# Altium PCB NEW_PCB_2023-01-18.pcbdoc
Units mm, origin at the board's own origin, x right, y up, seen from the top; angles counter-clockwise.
Board outline 51.82 x 75.44 mm, 2 copper layers (Top Layer, Bottom Layer); 4 components, 20 nets, 43 pads, 0 vias.
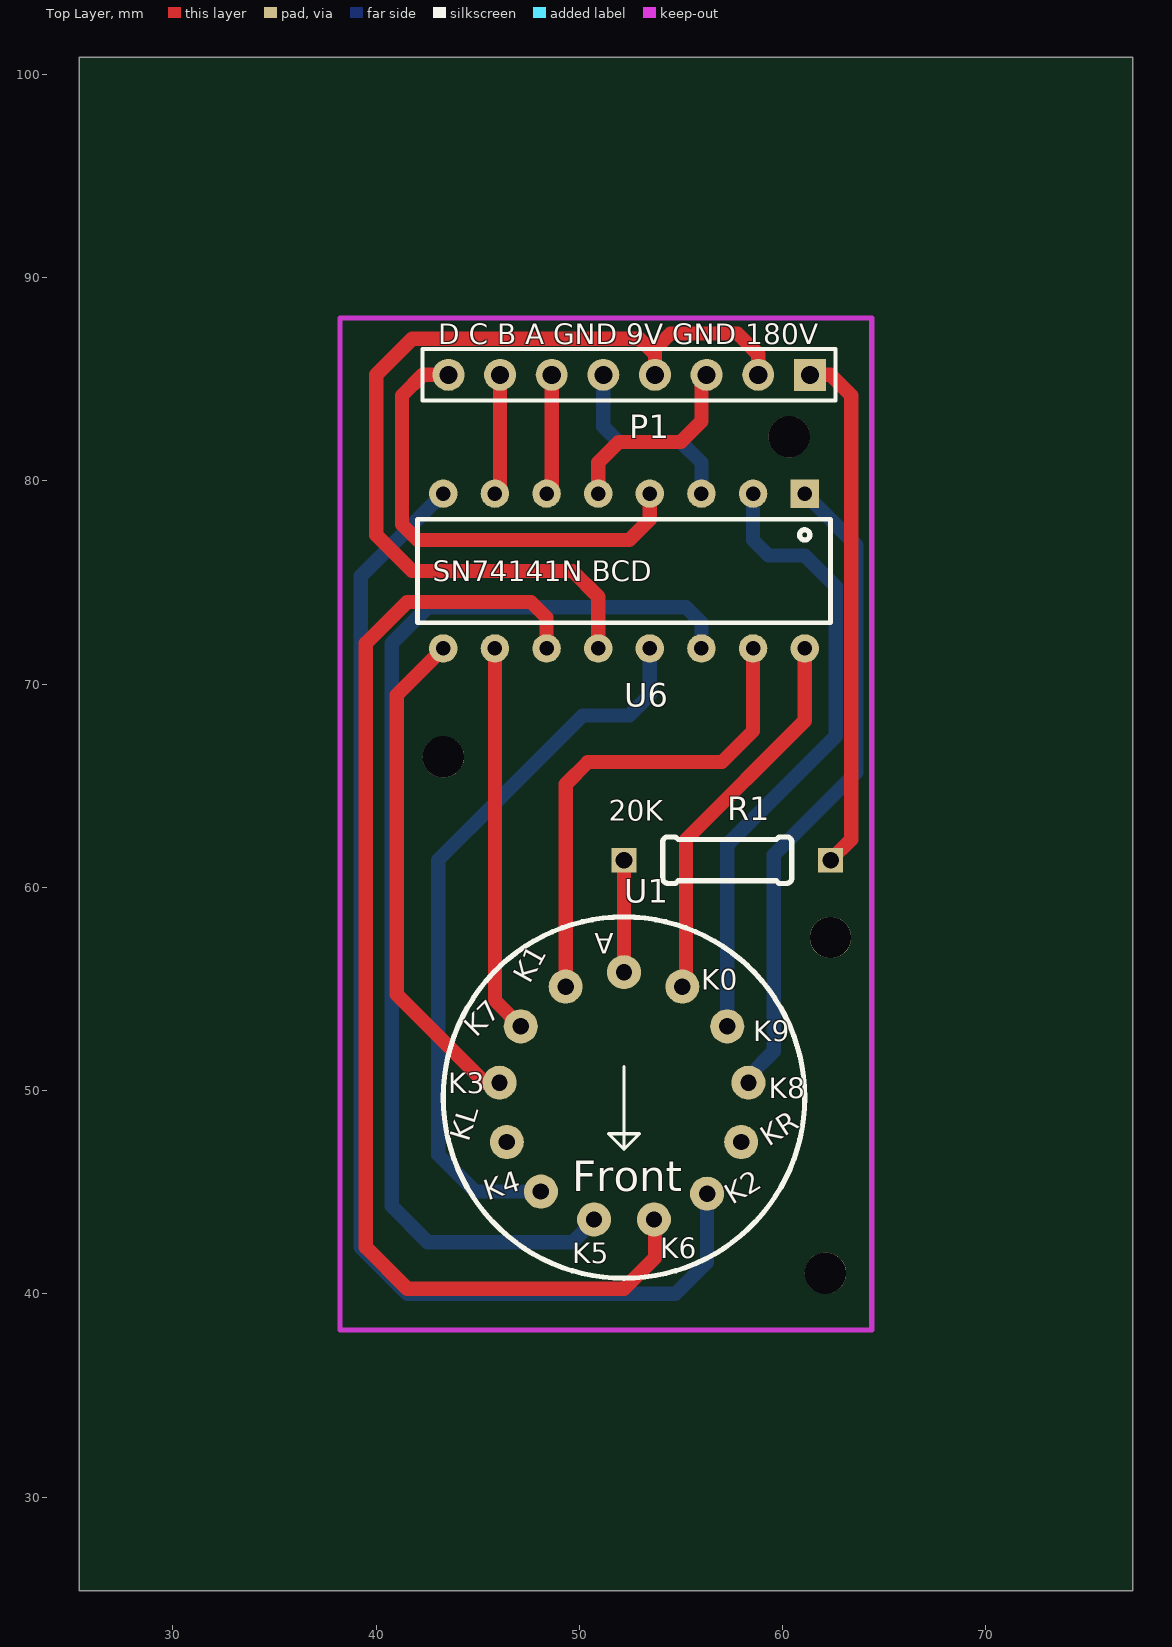
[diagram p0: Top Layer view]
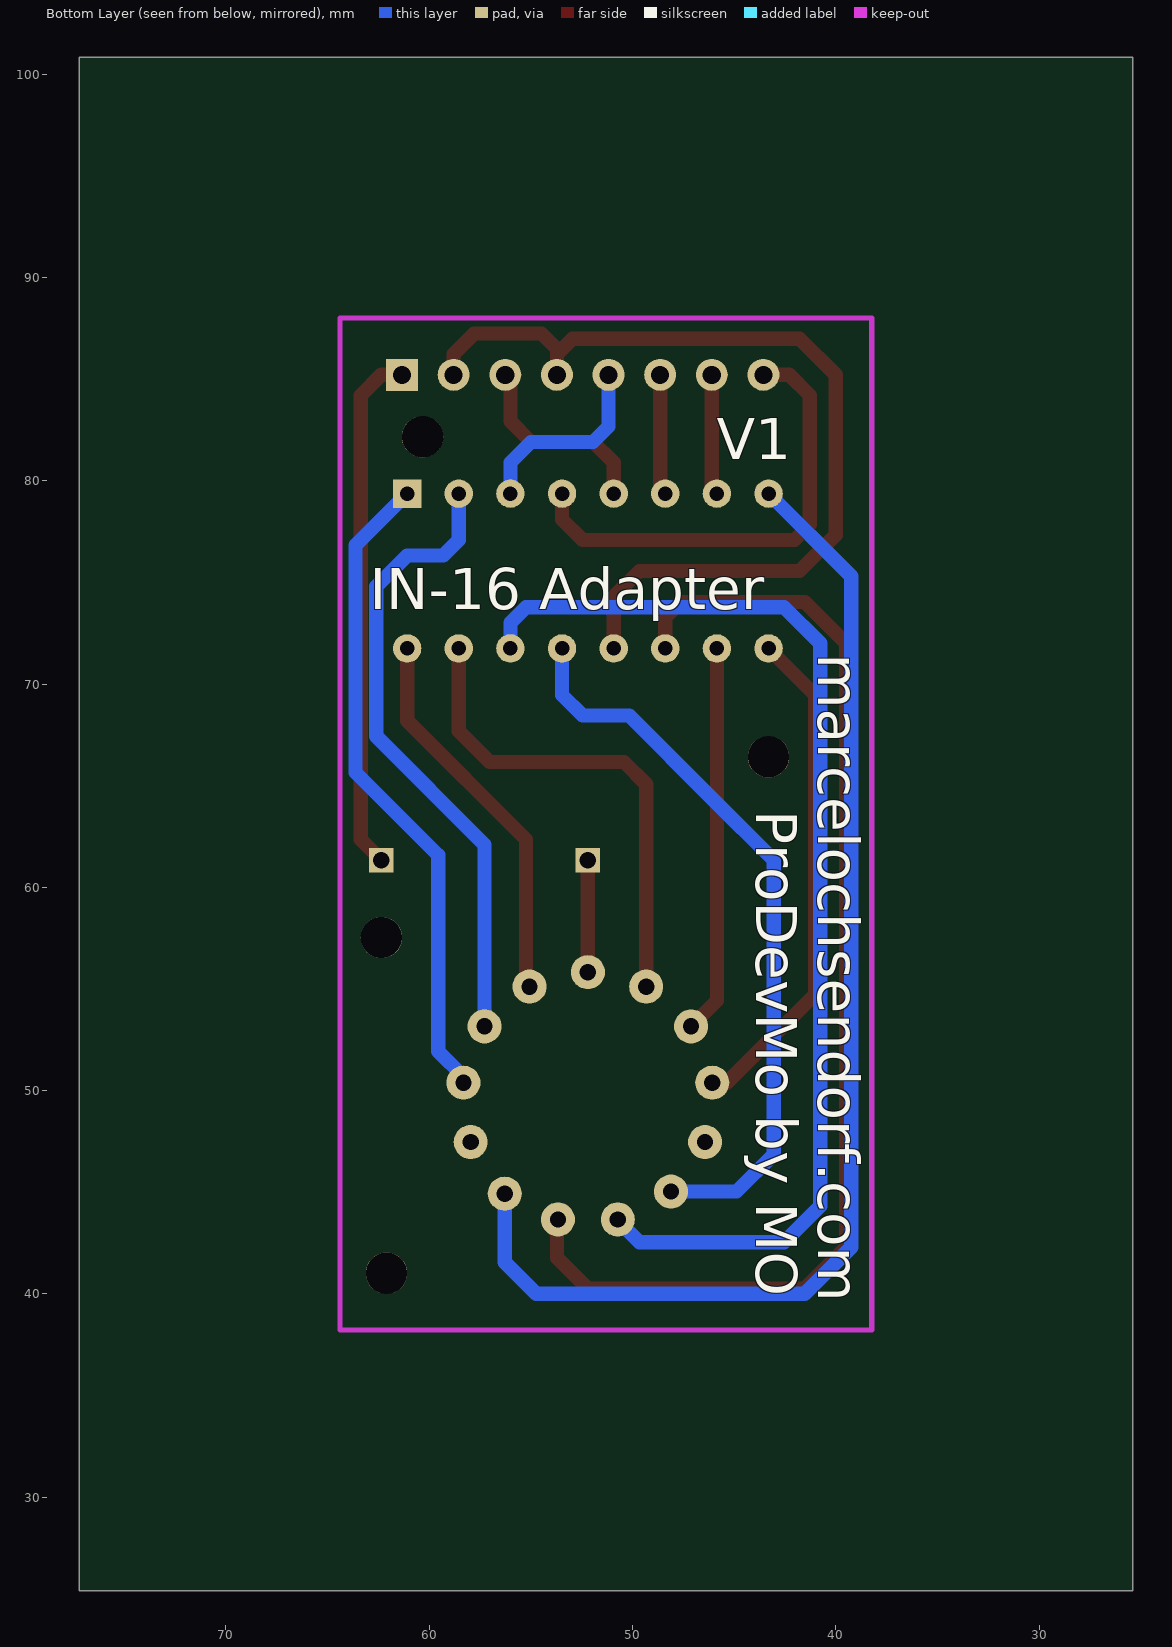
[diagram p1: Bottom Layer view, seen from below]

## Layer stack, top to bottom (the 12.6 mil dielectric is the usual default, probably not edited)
Top Layer: signal copper (thickness not stored)
Dielectric: dielectric 0.32, FR-4, Dk 4.8
Bottom Layer: signal copper (thickness not stored)

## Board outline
77.216,25.4 25.4,25.4 25.4,100.838 77.216,100.838

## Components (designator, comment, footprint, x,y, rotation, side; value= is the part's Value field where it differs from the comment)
P1 "Header2.54mm 1*8P" HDR-8X1/2.54 53.721,85.217 r180 top
R1 "RESISTOR" RTH025W 57.277,61.341 r0 top
U1 "IN-16" "IN-16 FOOTPRINT" 52.197,49.657 r0 top
U6 "SN74141 BCD to Decimal" DIP16 61.087,79.375 r180 top

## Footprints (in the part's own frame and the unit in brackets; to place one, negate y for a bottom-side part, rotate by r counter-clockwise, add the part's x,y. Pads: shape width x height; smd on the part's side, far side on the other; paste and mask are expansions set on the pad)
DIP16 [mil]
  rect 55x55 hole 28: 1(0,0)
  round 55 hole 28: 2(100,0) 3(200,0) 4(300,0) 5(400,0) 6(500,0) 7(600,0) 8(700,0) 9(700,300) 10(600,300) 11(500,300) 12(400,300) 13(300,300) 14(200,300) 15(100,300) 16(0,300)
  silkscreen extent -50,50 750,250
HDR-8X1/2.54 [mil]
  rect 62x62 hole 35: 1(-300,0)
  round 62 hole 35: 2(-200,0) 3(-100,0) 4(0,0) 5(100,0) 6(200,0) 7(300,0) 8(400,0)
  silkscreen extent -350,-50 450,50
"IN-16 FOOTPRINT" [mil]
  round 66 hole 31.5: 1(0,243) 2(-113,215) 3(-200,138) 4(-241,29) 5(-227,-86) 6(-161,-182) 7(-58,-236) 8(58,-236) 9(161,-186) 10(227,-86) 11(241,29) 12(200,138) 13(113,215)
  silkscreen extent -350,-350 350,350
RTH025W [mil]
  rect 47.7x47.7 hole 32: 1(-200,0) 2(200,0)
  silkscreen extent -125,-45 125,45

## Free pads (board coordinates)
  round 2.032 hole 2.032 unplated: ""(43.307,66.421) ""(60.325,82.169) ""(62.103,41.021) ""(62.357,57.531)

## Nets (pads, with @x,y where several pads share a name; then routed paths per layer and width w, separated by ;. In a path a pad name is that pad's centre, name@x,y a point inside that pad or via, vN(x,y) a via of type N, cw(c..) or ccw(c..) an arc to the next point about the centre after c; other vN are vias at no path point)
R1_2: P1.1 R1.2 | length 25.7
  Top Layer w0.7: P1.1 62.357,85.217 63.373,84.201 63.373,62.357 R1.2
U1_1: R1.1 U1.1 | length 5.5
  Top Layer w0.7: U1.1 R1.1
U1_2: U1.2 U6.15 | length 24.3
  Top Layer w0.7: U1.2 49.327,65.075 50.419,66.167 57.023,66.167 58.547,67.691 U6.15
U1_3: U1.3 U6.10 | length 19.1
  Top Layer w0.7: U6.10 45.847,54.432 U1.3
U1_4: U1.4 U6.9 | length 24.8
  Top Layer w0.7: U6.9 41.021,69.469 41.021,54.737 45.364,50.394 U1.4
U1_5: U1.5
U1_6: U1.6 U6.13 | length 36.4
  Bottom Layer w0.7: U1.6 44.882,45.034 43.053,46.863 43.053,61.341 46.101,64.389 50.165,68.453 52.451,68.453 53.467,69.469 U6.13
U1_7: U1.7 U6.14 | length 56.4
  Bottom Layer w0.7: U1.7 50.724,43.612 49.657,42.545 42.545,42.545 40.767,44.323 40.767,72.009 42.545,73.787 55.245,73.787 56.007,73.025 U6.14
U1_8: U1.8 U6.11 | length 58.9
  Top Layer w0.7: U6.11 48.387,73.279 47.625,74.041 41.529,74.041 39.497,72.009 39.497,42.291 41.529,40.259 52.197,40.259 53.721,41.783 53.721,43.612 U1.8
U1_9: U1.9 U6.8 | length 60.8
  Bottom Layer w0.7: U6.8 39.243,75.311 39.243,42.291 41.529,40.005 54.737,40.005 56.286,41.554 U1.9
U1_10: U1.10
U1_11: U1.11 U6.1 | length 32.2
  Bottom Layer w0.7: U1.11 58.318,50.698 59.563,51.943 59.563,61.595 63.627,65.659 63.627,76.835 U6.1
U1_12: U1.12 U6.2 | length 31.1
  Bottom Layer w0.7: U1.12 57.277,62.103 62.611,67.437 62.611,74.803 61.087,76.327 59.309,76.327 58.547,77.089 U6.2
U1_13: U1.13 U6.16 | length 19.1
  Top Layer w0.7: U1.13 55.245,55.296 55.245,62.357 61.087,68.199 U6.16
U6_3: P1.5 U6.3 | length 9.6
  Bottom Layer w0.7: P1.5 51.181,82.677 51.943,81.915 54.991,81.915 56.007,80.899 U6.3
U6_4: P1.8 U6.4 | length 23.3
  Top Layer w0.7: P1.8 42.291,85.217 41.275,84.201 41.275,77.851 42.037,77.089 52.451,77.089 53.467,78.105 U6.4
U6_5: P1.3 U6.5 | length 9.8
  Top Layer w0.7: U6.5 50.927,80.899 51.943,81.915 54.991,81.915 56.007,82.931 56.007,84.963 P1.3
U6_6: P1.6 U6.6 | length 5.9
  Top Layer w0.7: U6.6 48.641,79.629 P1.6
U6_7: P1.7 U6.7 | length 5.9
  Top Layer w0.7: U6.7 46.101,79.629 P1.7
U6_12: P1.2 P1.4 U6.12 | length 46.5
  Top Layer w0.7: U6.12 50.927,74.295 49.657,75.565 41.783,75.565 40.005,77.343 40.005,85.217 41.783,86.995 52.959,86.995 53.721,86.233 P1.4 53.721,86.487 54.483,87.249 57.785,87.249 58.801,86.233 P1.2

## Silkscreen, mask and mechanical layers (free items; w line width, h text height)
Top Overlay:
  text "D C B A GND 9V GND 180V" at 43.053,86.711 h1
  text "SN74141N BCD" at 42.799,75.065 h1
  text "20K" at 51.435,63.29 h1
Bottom Overlay:
  text "V1" at 45.856,81.061 h2.03
  text "IN-16 Adapter" at 62.934,73.695 h2.03
  text "marcelochsendorf.com" at 40.859,71.501 h2.03 r90
  text "ProDevMo by MO" at 43.921,63.789 h2.03 r90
